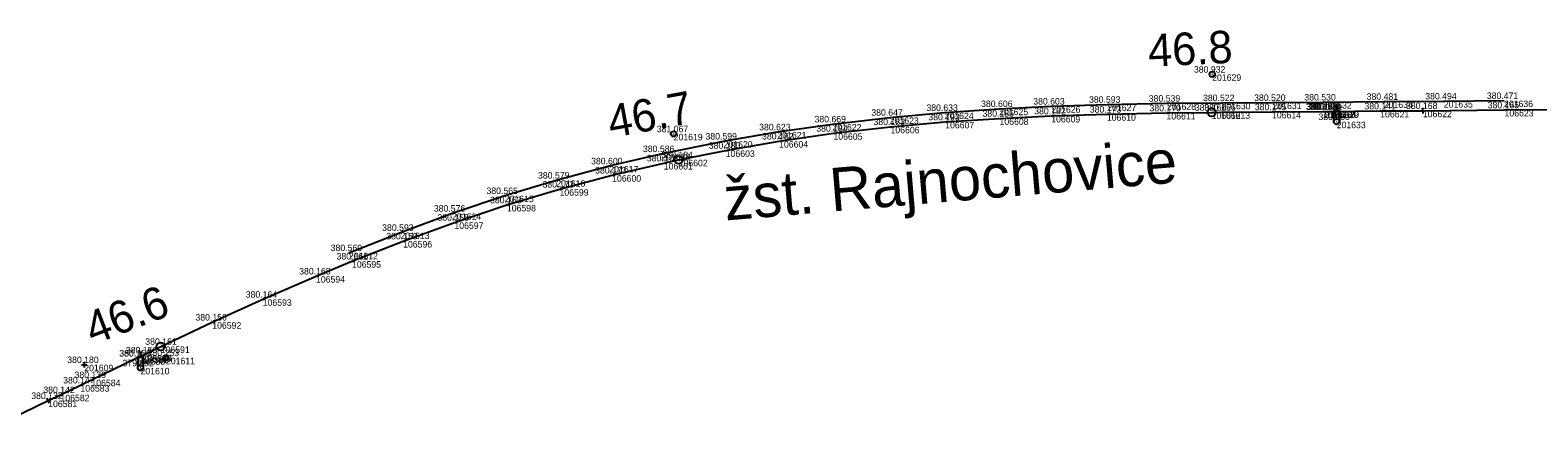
# Model space of a CAD drawing. Extents: x -545715 to -485912, y -1154994 to -1140055.
# Drawn here: x -509700 to -509421.8, y -1143232.4 to -1143159.8 of the extents above; entities that cross this region are included whole.
import ezdxf

# ---------------------------------------------------------------- set-up
doc = ezdxf.new("R2010")
doc.units = 0
for name, color, linetype in [('Vrstva 1', 7, 'Continuous'), ('Vrstva 14', 7, 'Continuous'), ('Vrstva 2', 7, 'Continuous'), ('Vrstva 23', 7, 'Continuous'), ('Vrstva 50', 7, 'Continuous'), ('Vrstva 60', 7, 'Continuous'), ('Vrstva 61', 7, 'Continuous'), ('Vrstva 7', 7, 'Continuous')]:
    doc.layers.add(name, color=color, linetype=linetype)

msp = doc.modelspace()

# ---------------------------------------------------------------- linework, layer by layer
at = {"layer": 'Vrstva 1'}
for p, q in [((-509541.26, -1143177.64), (-509531.17, -1143176.75)), ((-509531.17, -1143176.75), (-509521.15, -1143176.1)), ((-509521.15, -1143176.1), (-509511.61, -1143175.65)), ((-509511.61, -1143175.65), (-509501.34, -1143175.33)), ((-509501.34, -1143175.33), (-509490.34, -1143175.1)), ((-509490.34, -1143175.1), (-509482.01, -1143174.99)), ((-509482.01, -1143174.99), (-509480.27, -1143174.97)), ((-509480.27, -1143174.97), (-509470.87, -1143174.89)), ((-509470.87, -1143174.89), (-509461.51, -1143174.82)), ((-509461.51, -1143174.82), (-509460.22, -1143174.81)), ((-509460.22, -1143174.81), (-509460.19, -1143174.8)), ((-509460.19, -1143174.8), (-509450.91, -1143174.73)), ((-509450.91, -1143174.73), (-509443.04, -1143174.68)), ((-509443.04, -1143174.68), (-509427.97, -1143174.54)), ((-509427.97, -1143174.54), (-509417.89, -1143174.46)), ((-509561.82, -1143180.29), (-509551.79, -1143178.85)), ((-509551.79, -1143178.85), (-509541.26, -1143177.64)), ((-509580.35, -1143183.73), (-509571.66, -1143182)), ((-509571.66, -1143182), (-509561.82, -1143180.29)), ((-509592.62, -1143186.57), (-509583.09, -1143184.33)), ((-509583.09, -1143184.33), (-509580.35, -1143183.73)), ((-509602.33, -1143189.16), (-509592.62, -1143186.57)), ((-509612.04, -1143192.06), (-509602.33, -1143189.16)), ((-509621.72, -1143195.28), (-509612.04, -1143192.06)), ((-509631.19, -1143198.72), (-509621.72, -1143195.28)), ((-509640.62, -1143202.43), (-509631.19, -1143198.72)), ((-509647.26, -1143205.19), (-509640.62, -1143202.43)), ((-509657.09, -1143209.47), (-509647.26, -1143205.19)), ((-509666.4, -1143213.69), (-509657.09, -1143209.47)), ((-509675.91, -1143218.16), (-509666.4, -1143213.69)), ((-509679.24, -1143219.75), (-509675.91, -1143218.16)), ((-509688.7, -1143224.3), (-509680.46, -1143220.34)), ((-509680.46, -1143220.34), (-509679.24, -1143219.75)), ((-509694.4, -1143227.07), (-509690.73, -1143225.29)), ((-509690.73, -1143225.29), (-509688.7, -1143224.3)), ((-509705.55, -1143232.44), (-509696.67, -1143228.16)), ((-509696.67, -1143228.16), (-509694.4, -1143227.07))]:
    msp.add_line(p, q, dxfattribs=at)
at = {"layer": 'Vrstva 14'}
for p, q in [((-509521.22, -1143174.31), (-509511.57, -1143173.85)), ((-509511.57, -1143173.85), (-509501.27, -1143173.52)), ((-509501.27, -1143173.52), (-509490.25, -1143173.32)), ((-509490.25, -1143173.32), (-509480.2, -1143173.22)), ((-509480.2, -1143173.22), (-509470.78, -1143173.18)), ((-509470.78, -1143173.18), (-509461.52, -1143173.1)), ((-509461.52, -1143173.1), (-509450.25, -1143172.98)), ((-509450.25, -1143172.98), (-509439.17, -1143172.9)), ((-509439.17, -1143172.9), (-509428.07, -1143172.82)), ((-509551.97, -1143177.14), (-509541.4, -1143175.91)), ((-509541.4, -1143175.91), (-509531.27, -1143175.03)), ((-509531.27, -1143175.03), (-509521.22, -1143174.31)), ((-509572.06, -1143180.3), (-509562.13, -1143178.61)), ((-509562.13, -1143178.61), (-509551.97, -1143177.14)), ((-509583.57, -1143182.62), (-509572.06, -1143180.3)), ((-509602.93, -1143187.51), (-509593.15, -1143184.87)), ((-509593.15, -1143184.87), (-509583.57, -1143182.62)), ((-509612.44, -1143190.35), (-509602.93, -1143187.51)), ((-509622.15, -1143193.6), (-509612.44, -1143190.35)), ((-509631.68, -1143197.15), (-509622.15, -1143193.6)), ((-509641.19, -1143200.88), (-509631.68, -1143197.15))]:
    msp.add_line(p, q, dxfattribs=at)
at = {"layer": 'Vrstva 2'}
for p, q in [((-509443, -1143175.17), (-509443.07, -1143174.18)), ((-509696.43, -1143228.6), (-509696.9, -1143227.72))]:
    msp.add_line(p, q, dxfattribs=at)
at = {"layer": 'Vrstva 50'}
for p, q in [((-509458.94, -1143173.71), (-509458.94, -1143174.71)), ((-509458.89, -1143176.71), (-509458.99, -1143176.71)), ((-509679.64, -1143219.12), (-509679.64, -1143220.12)), ((-509679.59, -1143222.12), (-509679.69, -1143222.12))]:
    msp.add_line(p, q, dxfattribs=at)
for points in [[(-509459.45, -1143176.71), (-509459.44, -1143174.71), (-509458.44, -1143174.71), (-509458.44, -1143176.71)], [(-509680.15, -1143222.12), (-509680.14, -1143220.12), (-509679.14, -1143220.12), (-509679.14, -1143222.12)]]:
    msp.add_lwpolyline(points, dxfattribs=at)
for centre in [(-509458.94, -1143176.71), (-509679.64, -1143222.12)]:
    msp.add_circle(centre, 0.506, dxfattribs=at)
at = {"layer": 'Vrstva 60'}
for p, q in [((-509481.91, -1143167.97), (-509481.91, -1143167.97)), ((-509511.57, -1143173.85), (-509511.57, -1143173.85)), ((-509501.27, -1143173.52), (-509501.27, -1143173.52)), ((-509490.25, -1143173.32), (-509490.25, -1143173.32)), ((-509480.2, -1143173.22), (-509480.2, -1143173.22)), ((-509470.78, -1143173.18), (-509470.78, -1143173.18)), ((-509461.52, -1143173.1), (-509461.52, -1143173.1)), ((-509450.25, -1143172.98), (-509450.25, -1143172.98)), ((-509439.17, -1143172.9), (-509439.17, -1143172.9)), ((-509428.07, -1143172.82), (-509428.07, -1143172.82)), ((-509541.4, -1143175.91), (-509541.4, -1143175.91)), ((-509531.27, -1143175.03), (-509531.27, -1143175.03)), ((-509531.17, -1143176.75), (-509531.17, -1143176.75)), ((-509521.22, -1143174.31), (-509521.22, -1143174.31)), ((-509521.15, -1143176.1), (-509521.15, -1143176.1)), ((-509511.61, -1143175.65), (-509511.61, -1143175.65)), ((-509501.34, -1143175.33), (-509501.34, -1143175.33)), ((-509490.34, -1143175.1), (-509490.34, -1143175.1)), ((-509482.01, -1143174.99), (-509482.01, -1143174.99)), ((-509480.27, -1143174.97), (-509480.27, -1143174.97)), ((-509470.87, -1143174.89), (-509470.87, -1143174.89)), ((-509461.51, -1143174.82), (-509461.51, -1143174.82)), ((-509461.51, -1143174.82), (-509461.51, -1143174.82)), ((-509460.89, -1143174.81), (-509460.89, -1143174.81)), ((-509460.87, -1143174.81), (-509460.87, -1143174.81)), ((-509460.22, -1143174.81), (-509460.22, -1143174.81)), ((-509460.19, -1143174.8), (-509460.19, -1143174.8)), ((-509458.94, -1143176.71), (-509458.94, -1143176.71)), ((-509450.91, -1143174.73), (-509450.91, -1143174.73)), ((-509443.04, -1143174.68), (-509443.04, -1143174.68)), ((-509427.97, -1143174.54), (-509427.97, -1143174.54)), ((-509581.27, -1143178.95), (-509581.27, -1143178.95)), ((-509562.13, -1143178.61), (-509562.13, -1143178.61)), ((-509551.97, -1143177.14), (-509551.97, -1143177.14)), ((-509551.79, -1143178.85), (-509551.79, -1143178.85)), ((-509541.26, -1143177.64), (-509541.26, -1143177.64)), ((-509572.06, -1143180.3), (-509572.06, -1143180.3)), ((-509571.66, -1143182), (-509571.66, -1143182)), ((-509561.82, -1143180.29), (-509561.82, -1143180.29)), ((-509593.15, -1143184.87), (-509593.15, -1143184.87)), ((-509583.57, -1143182.62), (-509583.57, -1143182.62)), ((-509583.09, -1143184.33), (-509583.09, -1143184.33)), ((-509580.35, -1143183.73), (-509580.35, -1143183.73)), ((-509602.93, -1143187.51), (-509602.93, -1143187.51)), ((-509592.62, -1143186.57), (-509592.62, -1143186.57)), ((-509612.44, -1143190.35), (-509612.44, -1143190.35)), ((-509602.33, -1143189.16), (-509602.33, -1143189.16)), ((-509612.04, -1143192.06), (-509612.04, -1143192.06)), ((-509622.15, -1143193.6), (-509622.15, -1143193.6)), ((-509621.72, -1143195.28), (-509621.72, -1143195.28)), ((-509631.68, -1143197.15), (-509631.68, -1143197.15)), ((-509631.19, -1143198.72), (-509631.19, -1143198.72)), ((-509641.19, -1143200.88), (-509641.19, -1143200.88)), ((-509640.62, -1143202.43), (-509640.62, -1143202.43)), ((-509647.26, -1143205.19), (-509647.26, -1143205.19)), ((-509657.09, -1143209.47), (-509657.09, -1143209.47)), ((-509666.4, -1143213.69), (-509666.4, -1143213.69)), ((-509675.91, -1143218.16), (-509675.91, -1143218.16)), ((-509680.46, -1143220.34), (-509680.46, -1143220.34)), ((-509680.42, -1143220.32), (-509680.42, -1143220.32)), ((-509679.82, -1143220.03), (-509679.82, -1143220.03)), ((-509679.79, -1143220.02), (-509679.79, -1143220.02)), ((-509679.24, -1143219.75), (-509679.24, -1143219.75)), ((-509679.23, -1143219.75), (-509679.23, -1143219.75)), ((-509674.95, -1143220.25), (-509674.95, -1143220.25)), ((-509690.02, -1143221.53), (-509690.02, -1143221.53)), ((-509679.64, -1143222.12), (-509679.64, -1143222.12)), ((-509690.73, -1143225.29), (-509690.73, -1143225.29)), ((-509688.7, -1143224.3), (-509688.7, -1143224.3)), ((-509696.67, -1143228.16), (-509696.67, -1143228.16)), ((-509694.4, -1143227.07), (-509694.4, -1143227.07))]:
    msp.add_line(p, q, dxfattribs=at)
at = {"layer": 'Vrstva 7'}
for p, q in [((-509481.96, -1143167.97), (-509481.86, -1143167.97)), ((-509581.32, -1143178.95), (-509581.22, -1143178.95)), ((-509690.02, -1143221.03), (-509690.02, -1143222.03)), ((-509674.99, -1143220.25), (-509674.9, -1143220.25)), ((-509690.52, -1143221.53), (-509689.52, -1143221.53))]:
    msp.add_line(p, q, dxfattribs=at)
for centre, radius in [((-509481.91, -1143167.97), 0.5), ((-509482.01, -1143174.99), 0.75), ((-509581.27, -1143178.95), 0.5), ((-509580.35, -1143183.73), 0.75), ((-509675.91, -1143218.16), 0.75), ((-509674.95, -1143220.25), 0.5)]:
    msp.add_circle(centre, radius, dxfattribs=at)

# ---------------------------------------------------------------- texts
at = {"layer": 'Vrstva 23'}
msp.add_text('žst. Rajnochovice', height=8, rotation=4.8217, dxfattribs=at).set_placement((-509571.68, -1143194.94))
at = {"layer": 'Vrstva 60'}
for s, p in [('201629', (-509481.91, -1143169.17)), ('201626', (-509511.57, -1143175.05)), ('201627', (-509501.27, -1143174.72)), ('201628', (-509490.25, -1143174.52)), ('201630', (-509480.2, -1143174.42)), ('201631', (-509470.78, -1143174.38)), ('201632', (-509461.52, -1143174.3)), ('201634', (-509450.25, -1143174.18)), ('201635', (-509439.17, -1143174.1)), ('201636', (-509428.07, -1143174.02)), ('201623', (-509541.4, -1143177.11)), ('201624', (-509531.27, -1143176.23)), ('106607', (-509531.17, -1143177.95)), ('201625', (-509521.22, -1143175.51)), ('106608', (-509521.15, -1143177.3)), ('106609', (-509511.61, -1143176.85)), ('106610', (-509501.34, -1143176.53)), ('106611', (-509490.34, -1143176.3)), ('106612', (-509482.01, -1143176.19)), ('106613', (-509480.27, -1143176.17)), ('106614', (-509470.87, -1143176.09)), ('106615', (-509461.51, -1143176.02)), ('106616', (-509461.51, -1143176.02)), ('106617', (-509460.89, -1143176.01)), ('106618', (-509460.87, -1143176.01)), ('106619', (-509460.22, -1143176.01)), ('106620', (-509460.19, -1143176)), ('201633', (-509458.94, -1143177.91)), ('106621', (-509450.91, -1143175.93)), ('106622', (-509443.04, -1143175.88)), ('106623', (-509427.97, -1143175.74)), ('201619', (-509581.27, -1143180.15)), ('201621', (-509562.13, -1143179.81)), ('201622', (-509551.97, -1143178.34)), ('106605', (-509551.79, -1143180.05)), ('106606', (-509541.26, -1143178.84)), ('201620', (-509572.06, -1143181.5)), ('106603', (-509571.66, -1143183.2)), ('106604', (-509561.82, -1143181.49)), ('201617', (-509593.15, -1143186.07)), ('201618', (-509583.57, -1143183.82)), ('106601', (-509583.09, -1143185.53)), ('106602', (-509580.35, -1143184.93)), ('201616', (-509602.93, -1143188.71)), ('106600', (-509592.62, -1143187.77)), ('201615', (-509612.44, -1143191.55)), ('106599', (-509602.33, -1143190.36)), ('106598', (-509612.04, -1143193.26)), ('201614', (-509622.15, -1143194.8)), ('106597', (-509621.72, -1143196.48)), ('201613', (-509631.68, -1143198.35)), ('106596', (-509631.19, -1143199.92)), ('201612', (-509641.19, -1143202.08)), ('106595', (-509640.62, -1143203.63)), ('106594', (-509647.26, -1143206.39)), ('106593', (-509657.09, -1143210.67)), ('106592', (-509666.4, -1143214.89)), ('106591', (-509675.91, -1143219.36)), ('106585', (-509680.46, -1143221.54)), ('106586', (-509680.42, -1143221.52)), ('106587', (-509679.82, -1143221.23)), ('106588', (-509679.79, -1143221.22)), ('106590', (-509679.23, -1143220.95)), ('106589', (-509679.24, -1143220.95)), ('201611', (-509674.95, -1143221.45)), ('201609', (-509690.02, -1143222.73)), ('201610', (-509679.64, -1143223.32)), ('106583', (-509690.73, -1143226.49)), ('106584', (-509688.7, -1143225.5)), ('106581', (-509696.67, -1143229.36)), ('106582', (-509694.4, -1143228.27))]:
    msp.add_text(s, height=1.2, dxfattribs=at).set_placement(p)
at = {"layer": 'Vrstva 61'}
for s, p in [('380.932', (-509485.28, -1143167.67)), ('380.633', (-509534.64, -1143174.73)), ('380.606', (-509524.55, -1143174.01)), ('380.603', (-509514.93, -1143173.55)), ('380.593', (-509504.64, -1143173.22)), ('380.173', (-509504.49, -1143175.03)), ('380.539', (-509493.62, -1143173.02)), ('380.170', (-509493.48, -1143174.8)), ('380.160', (-509485.11, -1143174.69)), ('380.522', (-509483.6, -1143172.92)), ('380.156', (-509483.38, -1143174.67)), ('380.520', (-509474.17, -1143172.88)), ('380.145', (-509474.04, -1143174.59)), ('380.530', (-509464.91, -1143172.8)), ('380.139', (-509464.62, -1143174.52)), ('380.141', (-509464.42, -1143174.52)), ('380.139', (-509463.98, -1143174.51)), ('380.141', (-509463.79, -1143174.51)), ('380.140', (-509463.35, -1143174.5)), ('380.139', (-509463.33, -1143174.51)), ('380.141', (-509453.82, -1143174.43)), ('380.481', (-509453.41, -1143172.68)), ('380.168', (-509446.15, -1143174.38)), ('380.494', (-509442.6, -1143172.6)), ('380.471', (-509431.24, -1143172.52)), ('380.165', (-509431.08, -1143174.24)), ('380.669', (-509555.28, -1143176.84)), ('380.647', (-509544.8, -1143175.61)), ('380.183', (-509544.4, -1143177.34)), ('380.193', (-509534.28, -1143176.45)), ('380.185', (-509524.29, -1143175.8)), ('380.182', (-509514.75, -1143175.35)), ('380.060', (-509462.31, -1143176.41)), ('381.067', (-509584.39, -1143178.65)), ('380.599', (-509575.4, -1143180)), ('380.623', (-509565.5, -1143178.31)), ('380.182', (-509564.96, -1143179.99)), ('380.184', (-509554.96, -1143178.55)), ('380.586', (-509586.94, -1143182.32)), ('380.184', (-509583.52, -1143183.43)), ('380.180', (-509574.79, -1143181.7)), ('380.600', (-509596.51, -1143184.57)), ('380.173', (-509595.76, -1143186.27)), ('380.178', (-509586.23, -1143184.03)), ('380.579', (-509606.3, -1143187.21)), ('380.173', (-509605.47, -1143188.86)), ('380.565', (-509615.81, -1143190.05)), ('380.163', (-509615.15, -1143191.76)), ('380.576', (-509625.52, -1143193.3)), ('380.593', (-509635.05, -1143196.85)), ('380.155', (-509624.86, -1143194.98)), ('380.159', (-509634.3, -1143198.42)), ('380.560', (-509644.55, -1143200.58)), ('380.161', (-509643.47, -1143202.13)), ('380.168', (-509650.37, -1143204.89)), ('380.164', (-509660.23, -1143209.17)), ('380.156', (-509669.51, -1143213.39)), ('380.156', (-509682.35, -1143219.45)), ('380.156', (-509682.34, -1143219.45)), ('380.161', (-509678.76, -1143217.86)), ('380.180', (-509693.16, -1143221.23)), ('380.156', (-509683.57, -1143220.04)), ('380.156', (-509683.54, -1143220.02)), ('379.992', (-509682.97, -1143221.82)), ('380.157', (-509682.93, -1143219.72)), ('380.156', (-509682.93, -1143219.73)), ('380.253', (-509678.34, -1143219.95)), ('380.147', (-509693.91, -1143224.99)), ('380.139', (-509691.81, -1143224)), ('380.132', (-509699.8, -1143227.86)), ('380.142', (-509697.57, -1143226.77))]:
    msp.add_text(s, height=1.2, dxfattribs=at).set_placement(p)
at = {"layer": 'Vrstva 7'}
for s, rotation, p in [('46.8', 2.7398, (-509493.63, -1143166.59)), ('46.7', 10.5315, (-509592.83, -1143179.73)), ('46.6', 21.0655, (-509688.43, -1143217.92))]:
    msp.add_text(s, height=6, rotation=rotation, dxfattribs=at).set_placement(p)

doc.saveas('drawing.dxf')
